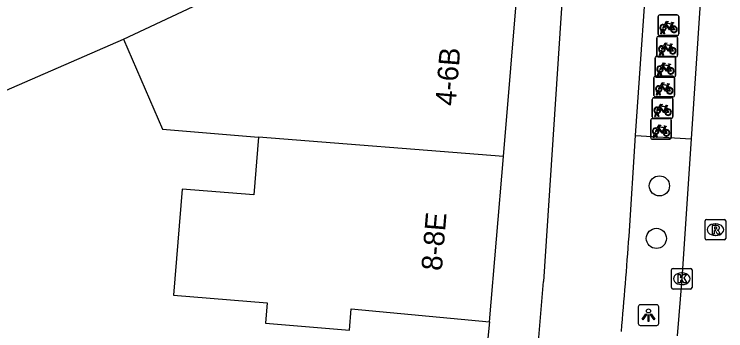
# Model space of a CAD drawing. Extents: x 161087 to 161922, y 382574 to 383873.
# Drawn here: x 161832.53 to 161867.05, y 382731.66 to 382747.01 of the extents above; entities that cross this region are included whole.
import ezdxf

# ---------------------------------------------------------------- set-up
doc = ezdxf.new("R2010")
doc.units = 0
for name, color, linetype in [('IMGEO_Berm_open', 7, 'Continuous'), ('IMGEO_Boom', 7, 'Continuous'), ('IMGEO_Fietsenrek', 7, 'Continuous'), ('IMGEO_Fietspad_gesloten', 7, 'Continuous'), ('IMGEO_Kolk', 7, 'Continuous'), ('IMGEO_Lichtpunt', 7, 'Continuous'), ('IMGEO_Pand', 7, 'Continuous'), ('IMGEO_Pand_nummerreeks', 7, 'Continuous'), ('IMGEO_Rijbaan_lokaal_gesloten', 7, 'Continuous'), ('IMGEO_Rioolput', 7, 'Continuous'), ('IMGEO_Voetpad_open', 7, 'Continuous')]:
    doc.layers.add(name, color=color, linetype=linetype)

msp = doc.modelspace()

# ---------------------------------------------------------------- linework, layer by layer
at = {"layer": 'IMGEO_Berm_open'}
msp.add_lwpolyline([(161862.676, 382741.127), (161865.365, 382740.966)], dxfattribs=at)
at = {"layer": 'IMGEO_Boom'}
for centre in [(161863.829, 382738.686), (161863.683, 382736.14)]:
    msp.add_circle(centre, 0.489, dxfattribs=at)
at = {"layer": 'IMGEO_Fietsenrek'}
for p, q in [((161863.843, 382746.979), (161864.684, 382746.979)), ((161864.684, 382746.979), (161863.843, 382746.979)), ((161863.768, 382746.054), (161863.768, 382746.895)), ((161863.768, 382746.895), (161863.768, 382746.054)), ((161864.768, 382746.904), (161864.768, 382746.063)), ((161864.768, 382746.063), (161864.768, 382746.904)), ((161864.455, 382746.528), (161864.491, 382746.433)), ((161863.784, 382745.939), (161864.625, 382745.939)), ((161864.625, 382745.939), (161863.784, 382745.939)), ((161864.693, 382745.979), (161863.852, 382745.979)), ((161863.852, 382745.979), (161864.693, 382745.979)), ((161863.895, 382746.063), (161863.934, 382746.223)), ((161863.929, 382746.063), (161863.895, 382746.063)), ((161863.964, 382746.211), (161863.929, 382746.063)), ((161864.006, 382746.235), (161864.005, 382746.239)), ((161864.047, 382746.063), (161864.013, 382746.205)), ((161864.037, 382746.246), (161864.038, 382746.239)), ((161864.045, 382746.209), (161864.08, 382746.063)), ((161864.08, 382746.063), (161864.047, 382746.063)), ((161863.709, 382745.014), (161863.709, 382745.855)), ((161863.709, 382745.855), (161863.709, 382745.014)), ((161864.709, 382745.864), (161864.709, 382745.023)), ((161864.709, 382745.023), (161864.709, 382745.864)), ((161864.396, 382745.488), (161864.432, 382745.393)), ((161863.618, 382744.038), (161863.618, 382744.879)), ((161863.618, 382744.879), (161863.618, 382744.038)), ((161863.693, 382744.963), (161864.534, 382744.963)), ((161864.534, 382744.963), (161863.693, 382744.963)), ((161864.634, 382744.939), (161863.793, 382744.939)), ((161863.793, 382744.939), (161864.634, 382744.939)), ((161863.836, 382745.023), (161863.875, 382745.183)), ((161863.87, 382745.023), (161863.836, 382745.023)), ((161863.905, 382745.171), (161863.87, 382745.023)), ((161863.947, 382745.195), (161863.946, 382745.199)), ((161863.988, 382745.023), (161863.954, 382745.165)), ((161863.978, 382745.206), (161863.979, 382745.199)), ((161863.986, 382745.169), (161864.021, 382745.023)), ((161864.021, 382745.023), (161863.988, 382745.023)), ((161864.618, 382744.888), (161864.618, 382744.047)), ((161864.618, 382744.047), (161864.618, 382744.888)), ((161863.745, 382744.047), (161863.784, 382744.207)), ((161863.814, 382744.195), (161863.779, 382744.047)), ((161863.856, 382744.219), (161863.855, 382744.223)), ((161863.897, 382744.047), (161863.863, 382744.189)), ((161863.887, 382744.23), (161863.888, 382744.223)), ((161863.895, 382744.193), (161863.93, 382744.047)), ((161864.305, 382744.512), (161864.341, 382744.417)), ((161863.562, 382743.079), (161863.562, 382743.92)), ((161863.562, 382743.92), (161863.562, 382743.079)), ((161863.637, 382744.004), (161864.478, 382744.004)), ((161864.478, 382744.004), (161863.637, 382744.004)), ((161864.543, 382743.963), (161863.702, 382743.963)), ((161863.702, 382743.963), (161864.543, 382743.963)), ((161863.779, 382744.047), (161863.745, 382744.047)), ((161863.93, 382744.047), (161863.897, 382744.047)), ((161864.562, 382743.929), (161864.562, 382743.088)), ((161864.562, 382743.088), (161864.562, 382743.929)), ((161864.249, 382743.553), (161864.285, 382743.458)), ((161863.689, 382743.088), (161863.728, 382743.248)), ((161863.758, 382743.236), (161863.723, 382743.088)), ((161863.8, 382743.26), (161863.799, 382743.264)), ((161863.841, 382743.088), (161863.807, 382743.23)), ((161863.831, 382743.271), (161863.832, 382743.264)), ((161863.839, 382743.234), (161863.874, 382743.088)), ((161863.484, 382742.039), (161863.484, 382742.88)), ((161863.484, 382742.88), (161863.484, 382742.039)), ((161863.559, 382742.964), (161864.4, 382742.964)), ((161864.4, 382742.964), (161863.559, 382742.964)), ((161864.487, 382743.004), (161863.646, 382743.004)), ((161863.646, 382743.004), (161864.487, 382743.004)), ((161863.723, 382743.088), (161863.689, 382743.088)), ((161863.874, 382743.088), (161863.841, 382743.088)), ((161864.484, 382742.889), (161864.484, 382742.048)), ((161864.484, 382742.048), (161864.484, 382742.889)), ((161864.171, 382742.513), (161864.207, 382742.418)), ((161863.611, 382742.048), (161863.65, 382742.208)), ((161863.68, 382742.196), (161863.645, 382742.048)), ((161863.722, 382742.22), (161863.721, 382742.224)), ((161863.763, 382742.048), (161863.729, 382742.19)), ((161863.753, 382742.231), (161863.754, 382742.224)), ((161863.761, 382742.194), (161863.796, 382742.048)), ((161863.407, 382741.03), (161863.407, 382741.871)), ((161863.407, 382741.871), (161863.407, 382741.03)), ((161863.482, 382741.955), (161864.323, 382741.955)), ((161864.323, 382741.955), (161863.482, 382741.955)), ((161864.409, 382741.964), (161863.568, 382741.964)), ((161863.568, 382741.964), (161864.409, 382741.964)), ((161863.645, 382742.048), (161863.611, 382742.048)), ((161863.796, 382742.048), (161863.763, 382742.048)), ((161864.407, 382741.88), (161864.407, 382741.039)), ((161864.407, 382741.039), (161864.407, 382741.88)), ((161864.094, 382741.504), (161864.13, 382741.409)), ((161863.534, 382741.039), (161863.573, 382741.199)), ((161863.603, 382741.187), (161863.568, 382741.039)), ((161863.645, 382741.211), (161863.644, 382741.215)), ((161863.686, 382741.039), (161863.652, 382741.181)), ((161863.676, 382741.222), (161863.677, 382741.215)), ((161863.684, 382741.185), (161863.719, 382741.039)), ((161864.332, 382740.955), (161863.491, 382740.955)), ((161863.491, 382740.955), (161864.332, 382740.955)), ((161863.568, 382741.039), (161863.534, 382741.039)), ((161863.719, 382741.039), (161863.686, 382741.039))]:
    msp.add_line(p, q, dxfattribs=at)
for points in [[(161864.081, 382746.505), (161864.176, 382746.669), (161864.262, 382746.655), (161864.264, 382746.646), (161864.208, 382746.635), (161864.181, 382746.59), (161864.437, 382746.549)], [(161864.437, 382746.549), (161864.462, 382746.598), (161864.456, 382746.602), (161864.433, 382746.606), (161864.421, 382746.613), (161864.42, 382746.616), (161864.422, 382746.621), (161864.517, 382746.606), (161864.519, 382746.596), (161864.509, 382746.583), (161864.497, 382746.577), (161864.483, 382746.583), (161864.455, 382746.528)], [(161864.102, 382746.453), (161864.05, 382746.363), (161864.01, 382746.338), (161864.011, 382746.385), (161864.066, 382746.479)], [(161864.377, 382746.261), (161864.327, 382746.261), (161864.136, 382746.512), (161864.117, 382746.48)], [(161864.424, 382746.524), (161864.167, 382746.565), (161864.15, 382746.536), (161864.317, 382746.316), (161864.424, 382746.524)], [(161864.472, 382746.426), (161864.442, 382746.503), (161864.333, 382746.285), (161864.376, 382746.285)], [(161864.406, 382746.285), (161864.526, 382746.284), (161864.482, 382746.398)], [(161864.502, 382746.405), (161864.557, 382746.26), (161864.407, 382746.26)], [(161864.022, 382745.465), (161864.117, 382745.629), (161864.203, 382745.615), (161864.205, 382745.606), (161864.149, 382745.595), (161864.122, 382745.55), (161864.378, 382745.509)], [(161864.378, 382745.509), (161864.403, 382745.558), (161864.397, 382745.562), (161864.374, 382745.566), (161864.362, 382745.573), (161864.361, 382745.576), (161864.363, 382745.581), (161864.458, 382745.566), (161864.46, 382745.556), (161864.45, 382745.543), (161864.438, 382745.537), (161864.424, 382745.543), (161864.396, 382745.488)], [(161864.043, 382745.413), (161863.991, 382745.323), (161863.951, 382745.298), (161863.952, 382745.345), (161864.007, 382745.439)], [(161864.318, 382745.221), (161864.268, 382745.221), (161864.077, 382745.472), (161864.058, 382745.44)], [(161864.365, 382745.484), (161864.108, 382745.525), (161864.091, 382745.496), (161864.258, 382745.276), (161864.365, 382745.484)], [(161864.413, 382745.386), (161864.383, 382745.463), (161864.274, 382745.245), (161864.317, 382745.245)], [(161864.347, 382745.245), (161864.467, 382745.244), (161864.423, 382745.358)], [(161864.443, 382745.365), (161864.498, 382745.22), (161864.348, 382745.22)], [(161863.931, 382744.489), (161864.026, 382744.653), (161864.112, 382744.639), (161864.114, 382744.63), (161864.058, 382744.619), (161864.031, 382744.574), (161864.287, 382744.533)], [(161864.274, 382744.508), (161864.017, 382744.549), (161864, 382744.52), (161864.167, 382744.3), (161864.274, 382744.508)], [(161864.287, 382744.533), (161864.312, 382744.582), (161864.306, 382744.586), (161864.283, 382744.59), (161864.271, 382744.597), (161864.27, 382744.6), (161864.272, 382744.605), (161864.367, 382744.59), (161864.369, 382744.58), (161864.359, 382744.567), (161864.347, 382744.561), (161864.333, 382744.567), (161864.305, 382744.512)], [(161863.952, 382744.437), (161863.9, 382744.347), (161863.86, 382744.322), (161863.861, 382744.369), (161863.916, 382744.463)], [(161864.227, 382744.245), (161864.177, 382744.245), (161863.986, 382744.496), (161863.967, 382744.464)], [(161864.322, 382744.41), (161864.292, 382744.487), (161864.183, 382744.269), (161864.226, 382744.269)], [(161864.256, 382744.269), (161864.376, 382744.268), (161864.332, 382744.382)], [(161864.352, 382744.389), (161864.407, 382744.244), (161864.257, 382744.244)], [(161863.896, 382743.478), (161863.844, 382743.388), (161863.804, 382743.363), (161863.805, 382743.41), (161863.86, 382743.504)], [(161863.875, 382743.53), (161863.97, 382743.694), (161864.056, 382743.68), (161864.058, 382743.671), (161864.002, 382743.66), (161863.975, 382743.615), (161864.231, 382743.574)], [(161864.171, 382743.286), (161864.121, 382743.286), (161863.93, 382743.537), (161863.911, 382743.505)], [(161864.218, 382743.549), (161863.961, 382743.59), (161863.944, 382743.561), (161864.111, 382743.341), (161864.218, 382743.549)], [(161864.266, 382743.451), (161864.236, 382743.528), (161864.127, 382743.31), (161864.17, 382743.31)], [(161864.231, 382743.574), (161864.256, 382743.623), (161864.25, 382743.627), (161864.227, 382743.631), (161864.215, 382743.638), (161864.214, 382743.641), (161864.216, 382743.646), (161864.311, 382743.631), (161864.313, 382743.621), (161864.303, 382743.608), (161864.291, 382743.602), (161864.277, 382743.608), (161864.249, 382743.553)], [(161864.2, 382743.31), (161864.32, 382743.309), (161864.276, 382743.423)], [(161864.296, 382743.43), (161864.351, 382743.285), (161864.201, 382743.285)], [(161863.818, 382742.438), (161863.766, 382742.348), (161863.726, 382742.323), (161863.727, 382742.37), (161863.782, 382742.464)], [(161863.797, 382742.49), (161863.892, 382742.654), (161863.978, 382742.64), (161863.98, 382742.631), (161863.924, 382742.62), (161863.897, 382742.575), (161864.153, 382742.534)], [(161864.093, 382742.246), (161864.043, 382742.246), (161863.852, 382742.497), (161863.833, 382742.465)], [(161864.14, 382742.509), (161863.883, 382742.55), (161863.866, 382742.521), (161864.033, 382742.301), (161864.14, 382742.509)], [(161864.188, 382742.411), (161864.158, 382742.488), (161864.049, 382742.27), (161864.092, 382742.27)], [(161864.153, 382742.534), (161864.178, 382742.583), (161864.172, 382742.587), (161864.149, 382742.591), (161864.137, 382742.598), (161864.136, 382742.601), (161864.138, 382742.606), (161864.233, 382742.591), (161864.235, 382742.581), (161864.225, 382742.568), (161864.213, 382742.562), (161864.199, 382742.568), (161864.171, 382742.513)], [(161864.122, 382742.27), (161864.242, 382742.269), (161864.198, 382742.383)], [(161864.218, 382742.39), (161864.273, 382742.245), (161864.123, 382742.245)], [(161863.741, 382741.429), (161863.689, 382741.339), (161863.649, 382741.314), (161863.65, 382741.361), (161863.705, 382741.455)], [(161863.72, 382741.481), (161863.815, 382741.645), (161863.901, 382741.631), (161863.903, 382741.622), (161863.847, 382741.611), (161863.82, 382741.566), (161864.076, 382741.525)], [(161864.016, 382741.237), (161863.966, 382741.237), (161863.775, 382741.488), (161863.756, 382741.456)], [(161864.063, 382741.5), (161863.806, 382741.541), (161863.789, 382741.512), (161863.956, 382741.292), (161864.063, 382741.5)], [(161864.111, 382741.402), (161864.081, 382741.479), (161863.972, 382741.261), (161864.015, 382741.261)], [(161864.076, 382741.525), (161864.101, 382741.574), (161864.095, 382741.578), (161864.072, 382741.582), (161864.06, 382741.589), (161864.059, 382741.592), (161864.061, 382741.597), (161864.156, 382741.582), (161864.158, 382741.572), (161864.148, 382741.559), (161864.136, 382741.553), (161864.122, 382741.559), (161864.094, 382741.504)], [(161864.045, 382741.261), (161864.165, 382741.26), (161864.121, 382741.374)], [(161864.141, 382741.381), (161864.196, 382741.236), (161864.046, 382741.236)]]:
    msp.add_lwpolyline(points, dxfattribs=at)
for centre, radius, start, end in [((161863.846, 382746.901), 0.0779, 92.4484, 184.2845), ((161863.846, 382746.901), 0.0779, 92.4484, 184.2845), ((161864.69, 382746.901), 0.0779, 2.4484, 94.2845), ((161864.69, 382746.901), 0.0779, 2.4484, 94.2845), ((161864.008, 382746.364), 0.159, 62.6766, 242.1369), ((161864.008, 382746.364), 0.129, 63.3192, 238.903), ((161863.988, 382746.235), 0.0499, 12.8025, 158.6934), ((161863.988, 382746.235), 0.0174, 12.8025, 163.4502), ((161864.008, 382746.364), 0.129, 283.6043, 43.4302), ((161864.008, 382746.364), 0.159, 283.5766, 46.6042), ((161864.535, 382746.28), 0.159, 113.3408, 178.3217), ((161864.535, 382746.28), 0.159, 187.0065, 105.7708), ((161864.535, 382746.28), 0.129, 113.923, 177.9556), ((161864.535, 382746.28), 0.129, 188.6715, 104.5883), ((161863.787, 382745.861), 0.0779, 92.4484, 184.2845), ((161863.787, 382745.861), 0.0779, 92.4484, 184.2845), ((161863.846, 382746.057), 0.0779, 182.4484, 274.2845), ((161863.846, 382746.057), 0.0779, 182.4484, 274.2845), ((161864.008, 382746.364), 0.159, 253.9967, 271.7867), ((161864.008, 382746.364), 0.129, 253.415, 269.0204), ((161864.631, 382745.861), 0.0779, 2.4484, 94.2845), ((161864.631, 382745.861), 0.0779, 2.4484, 94.2845), ((161864.69, 382746.057), 0.0779, 272.4484, 4.2845), ((161864.69, 382746.057), 0.0779, 272.4484, 4.2845), ((161863.949, 382745.324), 0.159, 62.6766, 242.1369), ((161863.949, 382745.324), 0.129, 63.3192, 238.903), ((161863.929, 382745.195), 0.0499, 12.8025, 158.6934), ((161863.949, 382745.324), 0.129, 283.6043, 43.4302), ((161863.949, 382745.324), 0.159, 283.5766, 46.6042), ((161864.476, 382745.24), 0.159, 113.3408, 178.3217), ((161864.476, 382745.24), 0.159, 187.0065, 105.7708), ((161864.476, 382745.24), 0.129, 113.923, 177.9556), ((161864.476, 382745.24), 0.129, 188.6715, 104.5883), ((161863.696, 382744.885), 0.0779, 92.4484, 184.2845), ((161863.696, 382744.885), 0.0779, 92.4484, 184.2845), ((161863.787, 382745.017), 0.0779, 182.4484, 274.2845), ((161863.787, 382745.017), 0.0779, 182.4484, 274.2845), ((161863.949, 382745.324), 0.159, 253.9967, 271.7867), ((161863.929, 382745.195), 0.0174, 12.8025, 163.4502), ((161863.949, 382745.324), 0.129, 253.415, 269.0204), ((161864.54, 382744.885), 0.0779, 2.4484, 94.2845), ((161864.54, 382744.885), 0.0779, 2.4484, 94.2845), ((161864.631, 382745.017), 0.0779, 272.4484, 4.2845), ((161864.631, 382745.017), 0.0779, 272.4484, 4.2845), ((161863.858, 382744.348), 0.159, 62.6766, 242.1369), ((161863.858, 382744.348), 0.129, 63.3192, 238.903), ((161863.838, 382744.219), 0.0499, 12.8025, 158.6934), ((161863.858, 382744.348), 0.159, 253.9967, 271.7867), ((161863.838, 382744.219), 0.0174, 12.8025, 163.4502), ((161863.858, 382744.348), 0.129, 253.415, 269.0204), ((161863.858, 382744.348), 0.129, 283.6043, 43.4302), ((161863.858, 382744.348), 0.159, 283.5766, 46.6042), ((161864.385, 382744.264), 0.159, 113.3408, 178.3217), ((161864.385, 382744.264), 0.159, 187.0065, 105.7708), ((161864.385, 382744.264), 0.129, 113.923, 177.9556), ((161864.385, 382744.264), 0.129, 188.6715, 104.5883), ((161863.64, 382743.926), 0.0779, 92.4484, 184.2845), ((161863.64, 382743.926), 0.0779, 92.4484, 184.2845), ((161863.696, 382744.041), 0.0779, 182.4484, 274.2845), ((161863.696, 382744.041), 0.0779, 182.4484, 274.2845), ((161864.484, 382743.926), 0.0779, 2.4484, 94.2845), ((161864.484, 382743.926), 0.0779, 2.4484, 94.2845), ((161864.54, 382744.041), 0.0779, 272.4484, 4.2845), ((161864.54, 382744.041), 0.0779, 272.4484, 4.2845), ((161863.802, 382743.389), 0.159, 62.6766, 242.1369), ((161863.802, 382743.389), 0.129, 63.3192, 238.903), ((161863.802, 382743.389), 0.159, 283.5766, 46.6042), ((161863.782, 382743.26), 0.0499, 12.8025, 158.6934), ((161863.802, 382743.389), 0.159, 253.9967, 271.7867), ((161863.782, 382743.26), 0.0174, 12.8025, 163.4502), ((161863.802, 382743.389), 0.129, 253.415, 269.0204), ((161863.802, 382743.389), 0.129, 283.6043, 43.4302), ((161864.329, 382743.305), 0.159, 113.3408, 178.3217), ((161864.329, 382743.305), 0.159, 187.0065, 105.7708), ((161864.329, 382743.305), 0.129, 113.923, 177.9556), ((161864.329, 382743.305), 0.129, 188.6715, 104.5883), ((161863.562, 382742.886), 0.0779, 92.4484, 184.2845), ((161863.562, 382742.886), 0.0779, 92.4484, 184.2845), ((161863.64, 382743.082), 0.0779, 182.4484, 274.2845), ((161863.64, 382743.082), 0.0779, 182.4484, 274.2845), ((161864.406, 382742.886), 0.0779, 2.4484, 94.2845), ((161864.406, 382742.886), 0.0779, 2.4484, 94.2845), ((161864.484, 382743.082), 0.0779, 272.4484, 4.2845), ((161864.484, 382743.082), 0.0779, 272.4484, 4.2845), ((161863.724, 382742.349), 0.159, 62.6766, 242.1369), ((161863.724, 382742.349), 0.129, 63.3192, 238.903), ((161863.724, 382742.349), 0.159, 283.5766, 46.6042), ((161863.704, 382742.22), 0.0499, 12.8025, 158.6934), ((161863.724, 382742.349), 0.159, 253.9967, 271.7867), ((161863.704, 382742.22), 0.0174, 12.8025, 163.4502), ((161863.724, 382742.349), 0.129, 253.415, 269.0204), ((161863.724, 382742.349), 0.129, 283.6043, 43.4302), ((161864.251, 382742.265), 0.159, 113.3408, 178.3217), ((161864.251, 382742.265), 0.159, 187.0065, 105.7708), ((161864.251, 382742.265), 0.129, 113.923, 177.9556), ((161864.251, 382742.265), 0.129, 188.6715, 104.5883), ((161863.485, 382741.877), 0.0779, 92.4484, 184.2845), ((161863.485, 382741.877), 0.0779, 92.4484, 184.2845), ((161863.562, 382742.042), 0.0779, 182.4484, 274.2845), ((161863.562, 382742.042), 0.0779, 182.4484, 274.2845), ((161864.329, 382741.877), 0.0779, 2.4484, 94.2845), ((161864.329, 382741.877), 0.0779, 2.4484, 94.2845), ((161864.406, 382742.042), 0.0779, 272.4484, 4.2845), ((161864.406, 382742.042), 0.0779, 272.4484, 4.2845), ((161863.647, 382741.34), 0.159, 62.6766, 242.1369), ((161863.647, 382741.34), 0.129, 63.3192, 238.903), ((161863.647, 382741.34), 0.129, 283.6043, 43.4302), ((161863.647, 382741.34), 0.159, 283.5766, 46.6042), ((161863.627, 382741.211), 0.0499, 12.8025, 158.6934), ((161863.647, 382741.34), 0.159, 253.9967, 271.7867), ((161863.627, 382741.211), 0.0174, 12.8025, 163.4502), ((161863.647, 382741.34), 0.129, 253.415, 269.0204), ((161864.174, 382741.256), 0.159, 113.3408, 178.3217), ((161864.174, 382741.256), 0.159, 187.0065, 105.7708), ((161864.174, 382741.256), 0.129, 113.923, 177.9556), ((161864.174, 382741.256), 0.129, 188.6715, 104.5883), ((161863.485, 382741.033), 0.0779, 182.4484, 274.2845), ((161863.485, 382741.033), 0.0779, 182.4484, 274.2845), ((161864.329, 382741.033), 0.0779, 272.4484, 4.2845), ((161864.329, 382741.033), 0.0779, 272.4484, 4.2845)]:
    msp.add_arc(centre, radius, start, end, dxfattribs=at)
at = {"layer": 'IMGEO_Fietspad_gesloten'}
for points in [[(161864.583, 382830.709), (161862.087, 382792.658), (161859.377, 382751.761), (161858.204, 382734.049)], [(161862.676, 382741.127), (161863.359, 382751.101), (161864.144, 382763.393), (161864.145, 382763.415)], [(161862.359, 382736.252), (161862.676, 382741.127)]]:
    msp.add_lwpolyline(points, dxfattribs=at)
for centre, radius, start, end in [((161450.001, 382766.972), 413.501, 355.09598, 355.73945), ((161443.323, 382767.161), 416.2, 353.72536, 355.4368)]:
    msp.add_arc(centre, radius, start, end, dxfattribs=at)
at = {"layer": 'IMGEO_Kolk'}
for p, q in [((161864.415, 382733.756), (161864.415, 382734.608)), ((161864.49, 382734.682), (161865.342, 382734.682)), ((161865.416, 382734.608), (161865.416, 382733.756)), ((161864.903, 382734.462), (161864.928, 382734.462)), ((161864.926, 382733.902), (161864.901, 382733.902)), ((161865.342, 382733.682), (161864.49, 382733.682))]:
    msp.add_line(p, q, dxfattribs=at)
for points in [[(161864.415, 382733.756), (161864.415, 382734.608)], [(161864.49, 382734.682), (161865.342, 382734.682)], [(161865.416, 382734.608), (161865.416, 382733.756)], [(161864.736, 382734.382), (161864.859, 382734.382), (161864.859, 382734.231), (161864.989, 382734.382), (161865.153, 382734.382), (161865.007, 382734.231), (161865.16, 382733.982), (161865.008, 382733.982), (161864.923, 382734.146), (161864.859, 382734.079), (161864.859, 382733.982), (161864.736, 382733.982), (161864.736, 382734.382)], [(161865.342, 382733.682), (161864.49, 382733.682)]]:
    msp.add_lwpolyline(points, dxfattribs=at)
for centre, start, end in [((161864.492, 382734.606), 91.552, 178.448), ((161864.492, 382734.606), 91.552, 178.448), ((161865.34, 382734.606), 1.552, 88.448), ((161865.34, 382734.606), 1.552, 88.448), ((161864.492, 382733.758), 181.552, 268.448), ((161864.492, 382733.758), 181.552, 268.448), ((161865.34, 382733.758), 271.552, 358.448), ((161865.34, 382733.758), 271.552, 358.448)]:
    msp.add_arc(centre, 0.0765, start, end, dxfattribs=at)
for centre, major_axis, ratio, start_param, end_param in [((161864.902, 382734.182), (-0.387, 0.002), 0.722429, 4.712389, 7.853982), ((161864.927, 382734.182), (-0.39, 0.002), 0.717154, 1.570796, 4.712389)]:
    msp.add_ellipse(centre, major_axis=major_axis, ratio=ratio, start_param=start_param, end_param=end_param, dxfattribs=at)
at = {"layer": 'IMGEO_Lichtpunt'}
for p, q in [((161862.802, 382732.823), (161862.802, 382732.016)), ((161862.802, 382732.823), (161862.802, 382732.016)), ((161863.704, 382732.918), (161862.896, 382732.918)), ((161863.704, 382732.918), (161862.896, 382732.918)), ((161863.798, 382732.016), (161863.798, 382732.823)), ((161863.798, 382732.016), (161863.798, 382732.823)), ((161862.896, 382731.922), (161863.704, 382731.922)), ((161862.896, 382731.922), (161863.704, 382731.922))]:
    msp.add_line(p, q, dxfattribs=at)
for points in [[(161863.176, 382732.487), (161863.215, 382732.459), (161863.027, 382732.197), (161862.989, 382732.224), (161863.176, 382732.487)], [(161863.388, 382732.459), (161863.426, 382732.486), (161863.613, 382732.224), (161863.574, 382732.196), (161863.388, 382732.459)], [(161863.278, 382732.439), (161863.325, 382732.439), (161863.325, 382732.117), (161863.278, 382732.117), (161863.278, 382732.439)]]:
    msp.add_lwpolyline(points, dxfattribs=at)
msp.add_circle((161863.301, 382732.621), 0.0994, dxfattribs=at)
for centre, start, end in [((161862.896, 382732.823), 90, 180), ((161862.896, 382732.823), 90, 180), ((161863.704, 382732.823), 0, 90), ((161863.704, 382732.823), 0, 90), ((161862.896, 382732.016), 180, 270), ((161862.896, 382732.016), 180, 270), ((161863.704, 382732.016), 270, 0), ((161863.704, 382732.016), 270, 360)]:
    msp.add_arc(centre, 0.0946, start, end, dxfattribs=at)
at = {"layer": 'IMGEO_Pand'}
for points in [[(161846.952, 382781.596), (161826.285, 382772.036), (161824.514, 382775.865), (161808.664, 382768.534), (161811.318, 382763.682), (161822.714, 382743.348), (161824.517, 382740.025), (161831.129, 382742.893), (161837.83, 382745.8)], [(161837.83, 382745.8), (161845.906, 382749.6)], [(161856.266, 382740.106), (161856.985, 382748.691)], [(161837.83, 382745.8), (161839.726, 382741.438), (161844.387, 382741.057)], [(161844.387, 382741.057), (161844.162, 382738.247), (161840.674, 382738.525), (161840.263, 382733.383), (161844.794, 382733.021), (161844.714, 382732.022), (161848.8, 382731.696), (161848.881, 382732.717), (161855.594, 382732.092)], [(161856.266, 382740.106), (161844.387, 382741.057)], [(161855.594, 382732.092), (161856.266, 382740.106)]]:
    msp.add_lwpolyline(points, dxfattribs=at)
at = {"layer": 'IMGEO_Rijbaan_lokaal_gesloten'}
for points in [[(161865.994, 382750.69), (161865.801, 382747.557), (161865.365, 382740.966)], [(161865.365, 382740.966), (161864.916, 382734.182), (161864.696, 382731.416)]]:
    msp.add_lwpolyline(points, dxfattribs=at)
at = {"layer": 'IMGEO_Rioolput'}
for p, q in [((161866.048, 382736.137), (161866.048, 382736.989)), ((161866.123, 382737.063), (161866.975, 382737.063)), ((161867.049, 382736.989), (161867.049, 382736.137)), ((161866.536, 382736.843), (161866.561, 382736.843)), ((161866.559, 382736.283), (161866.534, 382736.283)), ((161866.975, 382736.063), (161866.123, 382736.063))]:
    msp.add_line(p, q, dxfattribs=at)
for points in [[(161866.048, 382736.137), (161866.048, 382736.989)], [(161866.123, 382737.063), (161866.975, 382737.063)], [(161867.049, 382736.989), (161867.049, 382736.137)], [(161866.637, 382736.761), (161866.385, 382736.763), (161866.385, 382736.363)], [(161866.563, 382736.682), (161866.509, 382736.682), (161866.509, 382736.601)], [(161866.509, 382736.601), (161866.561, 382736.601)], [(161866.385, 382736.363), (161866.509, 382736.363), (161866.509, 382736.525), (161866.52, 382736.525)], [(161866.567, 382736.496), (161866.638, 382736.363), (161866.778, 382736.363), (161866.713, 382736.489)], [(161866.975, 382736.063), (161866.123, 382736.063)]]:
    msp.add_lwpolyline(points, dxfattribs=at)
for centre, radius, start, end in [((161866.125, 382736.987), 0.0765, 91.552, 178.448), ((161866.125, 382736.987), 0.0765, 91.552, 178.448), ((161866.973, 382736.987), 0.0765, 1.552, 88.448), ((161866.973, 382736.987), 0.0765, 1.552, 88.448), ((161866.545, 382736.79), 0.19, 274.7715, 282.9687), ((161866.569, 382736.586), 0.0964, 77.0061, 93.1865), ((161866.583, 382736.643), 0.0378, 276.6634, 79.6772), ((161866.636, 382736.651), 0.109, 350.3612, 89.416), ((161866.634, 382736.651), 0.112, 277.5842, 350.9817), ((161866.519, 382736.472), 0.0533, 26.0293, 88.6989), ((161866.618, 382736.436), 0.108, 29.5134, 73.7905), ((161866.125, 382736.139), 0.0765, 181.552, 268.448), ((161866.125, 382736.139), 0.0765, 181.552, 268.448), ((161866.973, 382736.139), 0.0765, 271.552, 358.448), ((161866.973, 382736.139), 0.0765, 271.552, 358.448)]:
    msp.add_arc(centre, radius, start, end, dxfattribs=at)
for centre, major_axis, ratio, start_param, end_param in [((161866.535, 382736.563), (-0.387, 0.002), 0.722429, 4.712389, 7.853982), ((161866.56, 382736.563), (-0.39, 0.002), 0.717154, 1.570796, 4.712389)]:
    msp.add_ellipse(centre, major_axis=major_axis, ratio=ratio, start_param=start_param, end_param=end_param, dxfattribs=at)
at = {"layer": 'IMGEO_Voetpad_open'}
msp.add_lwpolyline([(161855.594, 382732.092), (161854.831, 382724.638)], dxfattribs=at)

# ---------------------------------------------------------------- texts
at = {"layer": 'IMGEO_Pand_nummerreeks'}
for s, rotation, p in [('4-6B', 85.2126, (161853.942, 382742.543)), ('8-8E', 85.2068, (161853.271, 382734.544))]:
    msp.add_text(s, height=1, rotation=rotation, dxfattribs=at).set_placement(p)

doc.saveas('drawing.dxf')
